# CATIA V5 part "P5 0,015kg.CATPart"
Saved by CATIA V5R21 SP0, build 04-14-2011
Part number: Part1.3
Material "Aluminium": density 2710 kg/m3, Young's modulus 7e+10 Pa, Poisson ratio 0.346, thermal expansion 2.36e-05 1/K
Bounding box of the stored display mesh (mm): x -17 to 17, y -8.5 to 8.5, z -17 to 17
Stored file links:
  C:\Users\HP\Desktop\Mes Fichiers\CATIA V5\Mini Projet\Projet 1\P5 0,015kg.CATPart
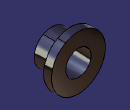
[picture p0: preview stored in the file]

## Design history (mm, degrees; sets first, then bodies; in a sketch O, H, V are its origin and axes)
AxisSystem1: origin (0, 0, 0), X (1, 0, 0), Y (0, 1, 0), Z (0, 0, 1)
Body1 (main body), material "Aluminium"
  Sketch1 on YZ plane of AxisSystem1, origin (0, 0, 0), H (0, 1, 0), V (0, 0, 1)
    point P1 (-8.5, 0)
    line L1 (-8.5, 0) -> (-8.5, 11)
    line L2 (-8.5, 11) -> (3.5, 11)
    line L3 (3.5, 11) -> (3.5, 17)
    line L4 (3.5, 17) -> (8.5, 17)
    line L5 (8.5, 17) -> (8.5, 0)
    point P6 (8.5, 0)
    line L6 (8.5, 0) -> (-8.5, 0)
    reference intersected line E1 through (0, 0) direction (0, 1) from ZX plane of AxisSystem1
    axis line L7 (-18.3502, 0) -> (22.6118, 0)
    point P7 (-18.3502, 0)
    length L2 = 12
    length L4 = 5
    distance L4 L6 = 17
    distance L2 L6 = 11
    coincidence: P1 H, P6 H, P7 H
    vertical: L1 V, L3 V, L5 V
    horizontal: L2 H, L4 H, L6 H, L7 H
    symmetry: L5 L1 E1
  Shaft1: profile Sketch1, axis Sketch1.L7, angle 360
  Sketch2 on face of Shaft1 from Sketch1.L1, origin (0, -8.5, 0), H (1, 0, 0), V (0, 0, 1)
    point P1 (0, 0)
    reference projected circle E1 centre (0, 0) radius 11 from edge [face of Shaft1 from Sketch1.L1 | face of Shaft1 from Sketch1.L2]
    concentricity: P1 E1
  Sketch3 on face of Shaft1 from Sketch1.L1, origin (0, -8.5, 0), H (1, 0, 0), V (0, 0, 1)
    point P1 (0, 0)
    reference projected point E1 (0, 0) from Sketch2.P1
    coincidence: E1 P1
  Hole1: placed by Sketch3, at (0, -8.5, 0) direction (0, 1, 0), diameter 16, through (limit type 3)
